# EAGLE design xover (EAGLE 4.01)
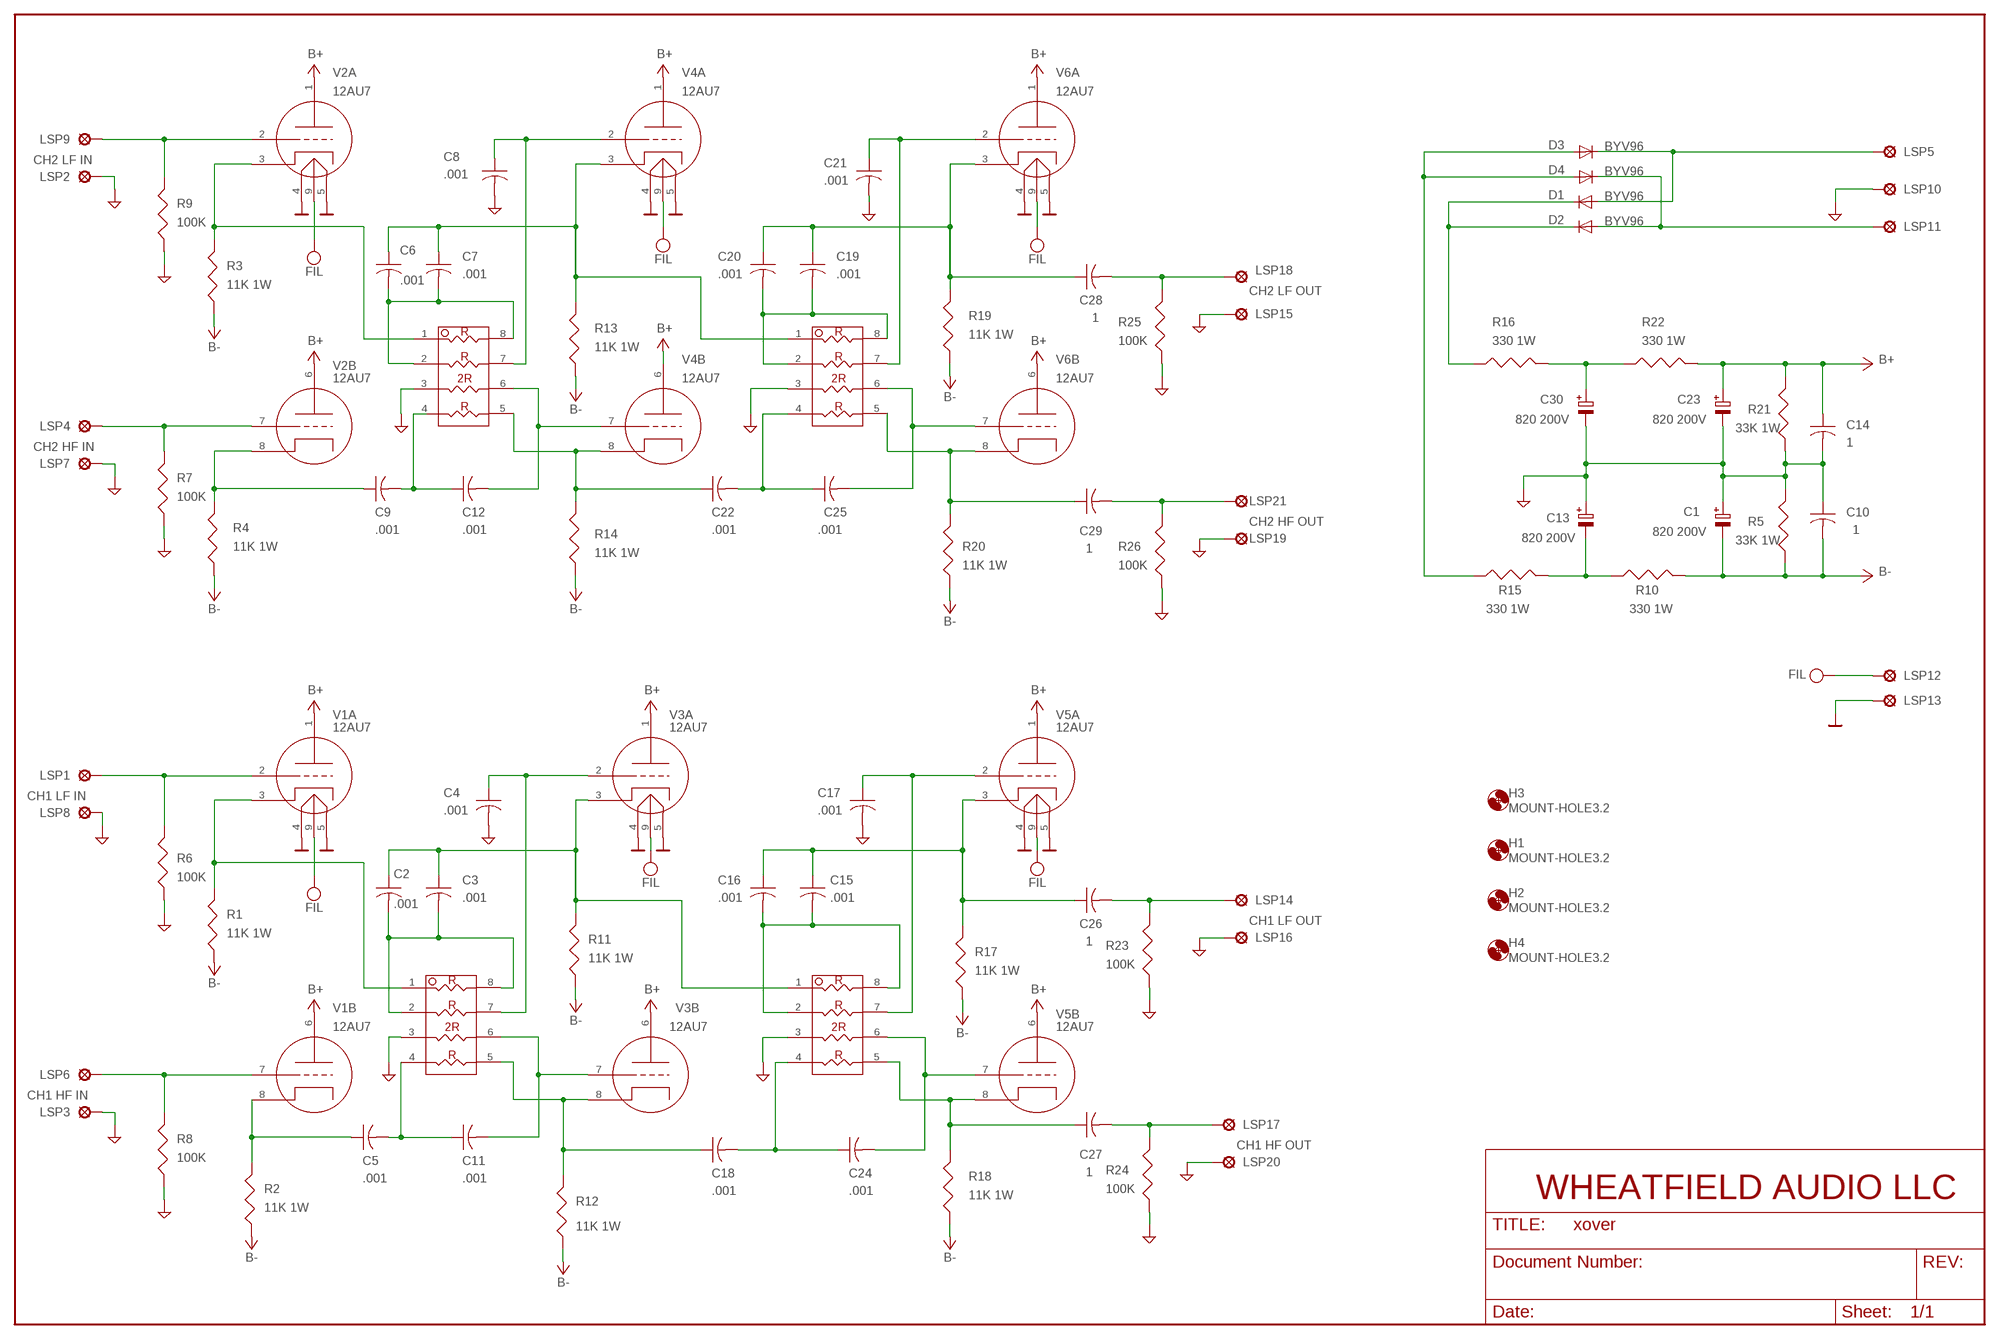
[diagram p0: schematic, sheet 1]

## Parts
C1  820 200V  C35SNAP  [C35SNAP]
C2  .001  C-US075-052X106  [C075-052X106]
C3  .001  C-US075-052X106  [C075-052X106]
C4  .001  C-US075-052X106  [C075-052X106]
C5  .001  C-US075-052X106  [C075-052X106]
C6  .001  C-US075-052X106  [C075-052X106]
C7  .001  C-US075-052X106  [C075-052X106]
C8  .001  C-US075-052X106  [C075-052X106]
C9  .001  C-US075-052X106  [C075-052X106]
C10  1  C-US275-154X316  [C275-154X316]
C11  .001  C-US075-052X106  [C075-052X106]
C12  .001  C-US075-052X106  [C075-052X106]
C13  820 200V  C35SNAP  [C35SNAP]
C14  1  C-US275-154X316  [C275-154X316]
C15  .001  C-US075-052X106  [C075-052X106]
C16  .001  C-US075-052X106  [C075-052X106]
C17  .001  C-US075-052X106  [C075-052X106]
C18  .001  C-US075-052X106  [C075-052X106]
C19  .001  C-US075-052X106  [C075-052X106]
C20  .001  C-US075-052X106  [C075-052X106]
C21  .001  C-US075-052X106  [C075-052X106]
C22  .001  C-US075-052X106  [C075-052X106]
C23  820 200V  C35SNAP  [C35SNAP]
C24  .001  C-US075-052X106  [C075-052X106]
C25  .001  C-US075-052X106  [C075-052X106]
C26  1  C-US275-154X316  [C275-154X316]
C27  1  C-US275-154X316  [C275-154X316]
C28  1  C-US275-154X316  [C275-154X316]
C29  1  C-US275-154X316  [C275-154X316]
C30  820 200V  C35SNAP  [C35SNAP]
D1  BYV96  [SOD57-10]
D2  BYV96  [SOD57-10]
D3  BYV96  [SOD57-10]
D4  BYV96  [SOD57-10]
H1  MOUNT-HOLE3.2  [3,2]
H2  MOUNT-HOLE3.2  [3,2]
H3  MOUNT-HOLE3.2  [3,2]
H4  MOUNT-HOLE3.2  [3,2]
LSP1  SE14  [SE14]
LSP2  SE14  [SE14]
LSP3  SE14  [SE14]
LSP4  SE14  [SE14]
LSP5  SE14  [SE14]
LSP6  SE14  [SE14]
LSP7  SE14  [SE14]
LSP8  SE14  [SE14]
LSP9  SE14  [SE14]
LSP10  SE14  [SE14]
LSP11  SE14  [SE14]
LSP12  SE14  [SE14]
LSP13  SE14  [SE14]
LSP14  SE14  [SE14]
LSP15  SE14  [SE14]
LSP16  SE14  [SE14]
LSP17  SE14  [SE14]
LSP18  SE14  [SE14]
LSP19  SE14  [SE14]
LSP20  SE14  [SE14]
LSP21  SE14  [SE14]
R1  11K 1W  R5W_MILLS  [R5W_MILLS]
R2  11K 1W  R5W_MILLS  [R5W_MILLS]
R3  11K 1W  R5W_MILLS  [R5W_MILLS]
R4  11K 1W  R5W_MILLS  [R5W_MILLS]
R5  33K 1W  R5W_MILLS  [R5W_MILLS]
R6  100K  R1/4W  [R1/4W]
R7  100K  R1/4W  [R1/4W]
R8  100K  R1/4W  [R1/4W]
R9  100K  R1/4W  [R1/4W]
R10  330 1W  R5W_MILLS  [R5W_MILLS]
R11  11K 1W  R5W_MILLS  [R5W_MILLS]
R12  11K 1W  R5W_MILLS  [R5W_MILLS]
R13  11K 1W  R5W_MILLS  [R5W_MILLS]
R14  11K 1W  R5W_MILLS  [R5W_MILLS]
R15  330 1W  R5W_MILLS  [R5W_MILLS]
R16  330 1W  R5W_MILLS  [R5W_MILLS]
R17  11K 1W  R5W_MILLS  [R5W_MILLS]
R18  11K 1W  R5W_MILLS  [R5W_MILLS]
R19  11K 1W  R5W_MILLS  [R5W_MILLS]
R20  11K 1W  R5W_MILLS  [R5W_MILLS]
R21  33K 1W  R5W_MILLS  [R5W_MILLS]
R22  330 1W  R5W_MILLS  [R5W_MILLS]
R23  100K  R1/4W  [R1/4W]
R24  100K  R1/4W  [R1/4W]
R25  100K  R1/4W  [R1/4W]
R26  100K  R1/4W  [R1/4W]
RM1  R_MODULE  [R_MODULE]
RM2  R_MODULE  [R_MODULE]
RM3  R_MODULE  [R_MODULE]
RM4  R_MODULE  [R_MODULE]
V1  12AU7  TRIODE_9A  [NOVAL_PCB]
V2  12AU7  TRIODE_9A  [NOVAL_PCB]
V3  12AU7  TRIODE_9A  [NOVAL_PCB]
V4  12AU7  TRIODE_9A  [NOVAL_PCB]
V5  12AU7  TRIODE_9A  [NOVAL_PCB]
V6  12AU7  TRIODE_9A  [NOVAL_PCB]

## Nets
0V: LSP13.MP V1.4 V1.5 V2.4 V2.5 V3.4 V3.5 V4.4 V4.5 V5.4 V5.5 V6.4 V6.5
GND: C1.1(+) C4.2 C8.2 C10.1 C13.1(+) C14.2 C17.2 C21.2 C23.2(-) C30.2(-) LSP2.MP LSP3.MP LSP7.MP LSP8.MP LSP10.MP LSP15.MP LSP16.MP LSP19.MP LSP20.MP R5.2 R6.1 R7.1 R8.1 R9.1 R21.1 R23.1 R24.1 R25.1 R26.1 RM1.3 RM2.3 RM3.3 RM4.3
N$1: LSP9.MP R9.2 V2.2
N$2: C9.2 C12.1 RM2.4
N$3: C19.1 C20.1 C28.1 R19.2 V6.3
N$4: LSP6.MP R8.2 V1.7
N$5: C22.1 R14.2 RM2.5 V4.8
N$6: C12.2 RM2.6 V4.7
N$7: LSP1.MP R6.2 V1.2
N$8: C19.2 C20.2 RM4.2 RM4.8
N$9: LSP4.MP R7.2 V2.7
N$10: C22.2 C25.1 RM4.4
N$11: C25.2 RM4.6 V6.7
N$12: C8.1 RM2.7 V4.2
N$13: C6.1 C7.1 R13.2 RM4.1 V4.3
N$14: C2.1 C3.1 R11.2 RM3.1 V3.3
N$15: C18.1 R12.2 RM1.5 V3.8
N$16: C9.1 R4.2 V2.8
N$17: C4.1 RM1.7 V3.2
N$19: C5.1 R2.2 V1.8
N$20: C15.1 C16.1 C26.1 R17.2 V5.3
N$21: C11.2 RM1.6 V3.7
N$22: C5.2 C11.1 RM1.4
N$23: C17.1 RM3.7 V5.2
N$24: R3.2 RM2.1 V2.3
N$25: R1.2 RM1.1 V1.3
N$26: C18.2 C24.1 RM3.4
N$27: C24.2 RM3.6 V5.7
N$28: C27.1 R18.2 RM3.5 V5.8
N$30: C28.2 LSP18.MP R25.2
N$31: C29.2 LSP21.MP R26.2
N$32: C26.2 LSP14.MP R23.2
N$33: C27.2 LSP17.MP R24.2
N$34: C6.2 C7.2 RM2.2 RM2.8
N$35: C21.1 RM4.7 V6.2
N$36: C29.1 R20.2 RM4.5 V6.8
N$39: C2.2 C3.2 RM1.2 RM1.8
N$40: D1.A D3.K(C) LSP5.MP
N$42: D1.K(C) D2.K(C) R16.1
N$43: D2.A D4.K(C) LSP11.MP
N$44: C30.1(+) R16.2 R22.1
N$46: D3.A D4.A R15.1
N$47: C13.2(-) R10.1 R15.2
N$50: C15.2 C16.2 RM3.2 RM3.8
V+: C14.1 C23.1(+) R21.2 R22.2 V1.1 V1.6 V2.1 V2.6 V3.1 V3.6 V4.1 V4.6 V5.1 V5.6 V6.1 V6.6 ; supply symbol labelled B+
V-: C1.2(-) C10.2 R1.1 R2.1 R3.1 R4.1 R5.1 R10.2 R11.1 R12.1 R13.1 R14.1 R17.1 R18.1 R19.1 R20.1 ; supply symbol labelled B-
VCC: LSP12.MP V1.9 V2.9 V3.9 V4.9 V5.9 V6.9 ; supply symbol labelled FIL

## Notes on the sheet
- CH2 LF IN
- CH2 LF OUT
- CH2 HF IN
- CH2 HF OUT
- CH1 LF IN
- CH1 LF OUT
- CH1 HF IN
- CH1 HF OUT
- WHEATFIELD AUDIO LLC

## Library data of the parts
C1 C13 C23 C30 = wheat:C35SNAP: CAP, 35MM SNAP MOUNT
C2-C12 C14-C22 C24-C29 = rcl:C-US: CAPACITOR, American symbol
D1-D4 = diode:BYV96: DIODE
H1-H4 = holes:MOUNT-HOLE: MOUNTING HOLE with drill center marker
LSP1-LSP21 = solpad:SE14: SOLDER PAD
R1-R5 R10-R22 = wheat:R5W_MILLS: RESISTOR, 5W WIREWOUND, MILLS
R6-R9 R23-R26 = wheat:R1/4W: RESISTOR, 1/4W THM
RM1-RM4 = wheat:R_MODULE: RESISTOR MODULE DIP8
V1-V6 = wheat:TRIODE_9A: TRIODE, BASE 9A 12AU7, 12AX7, ETC.

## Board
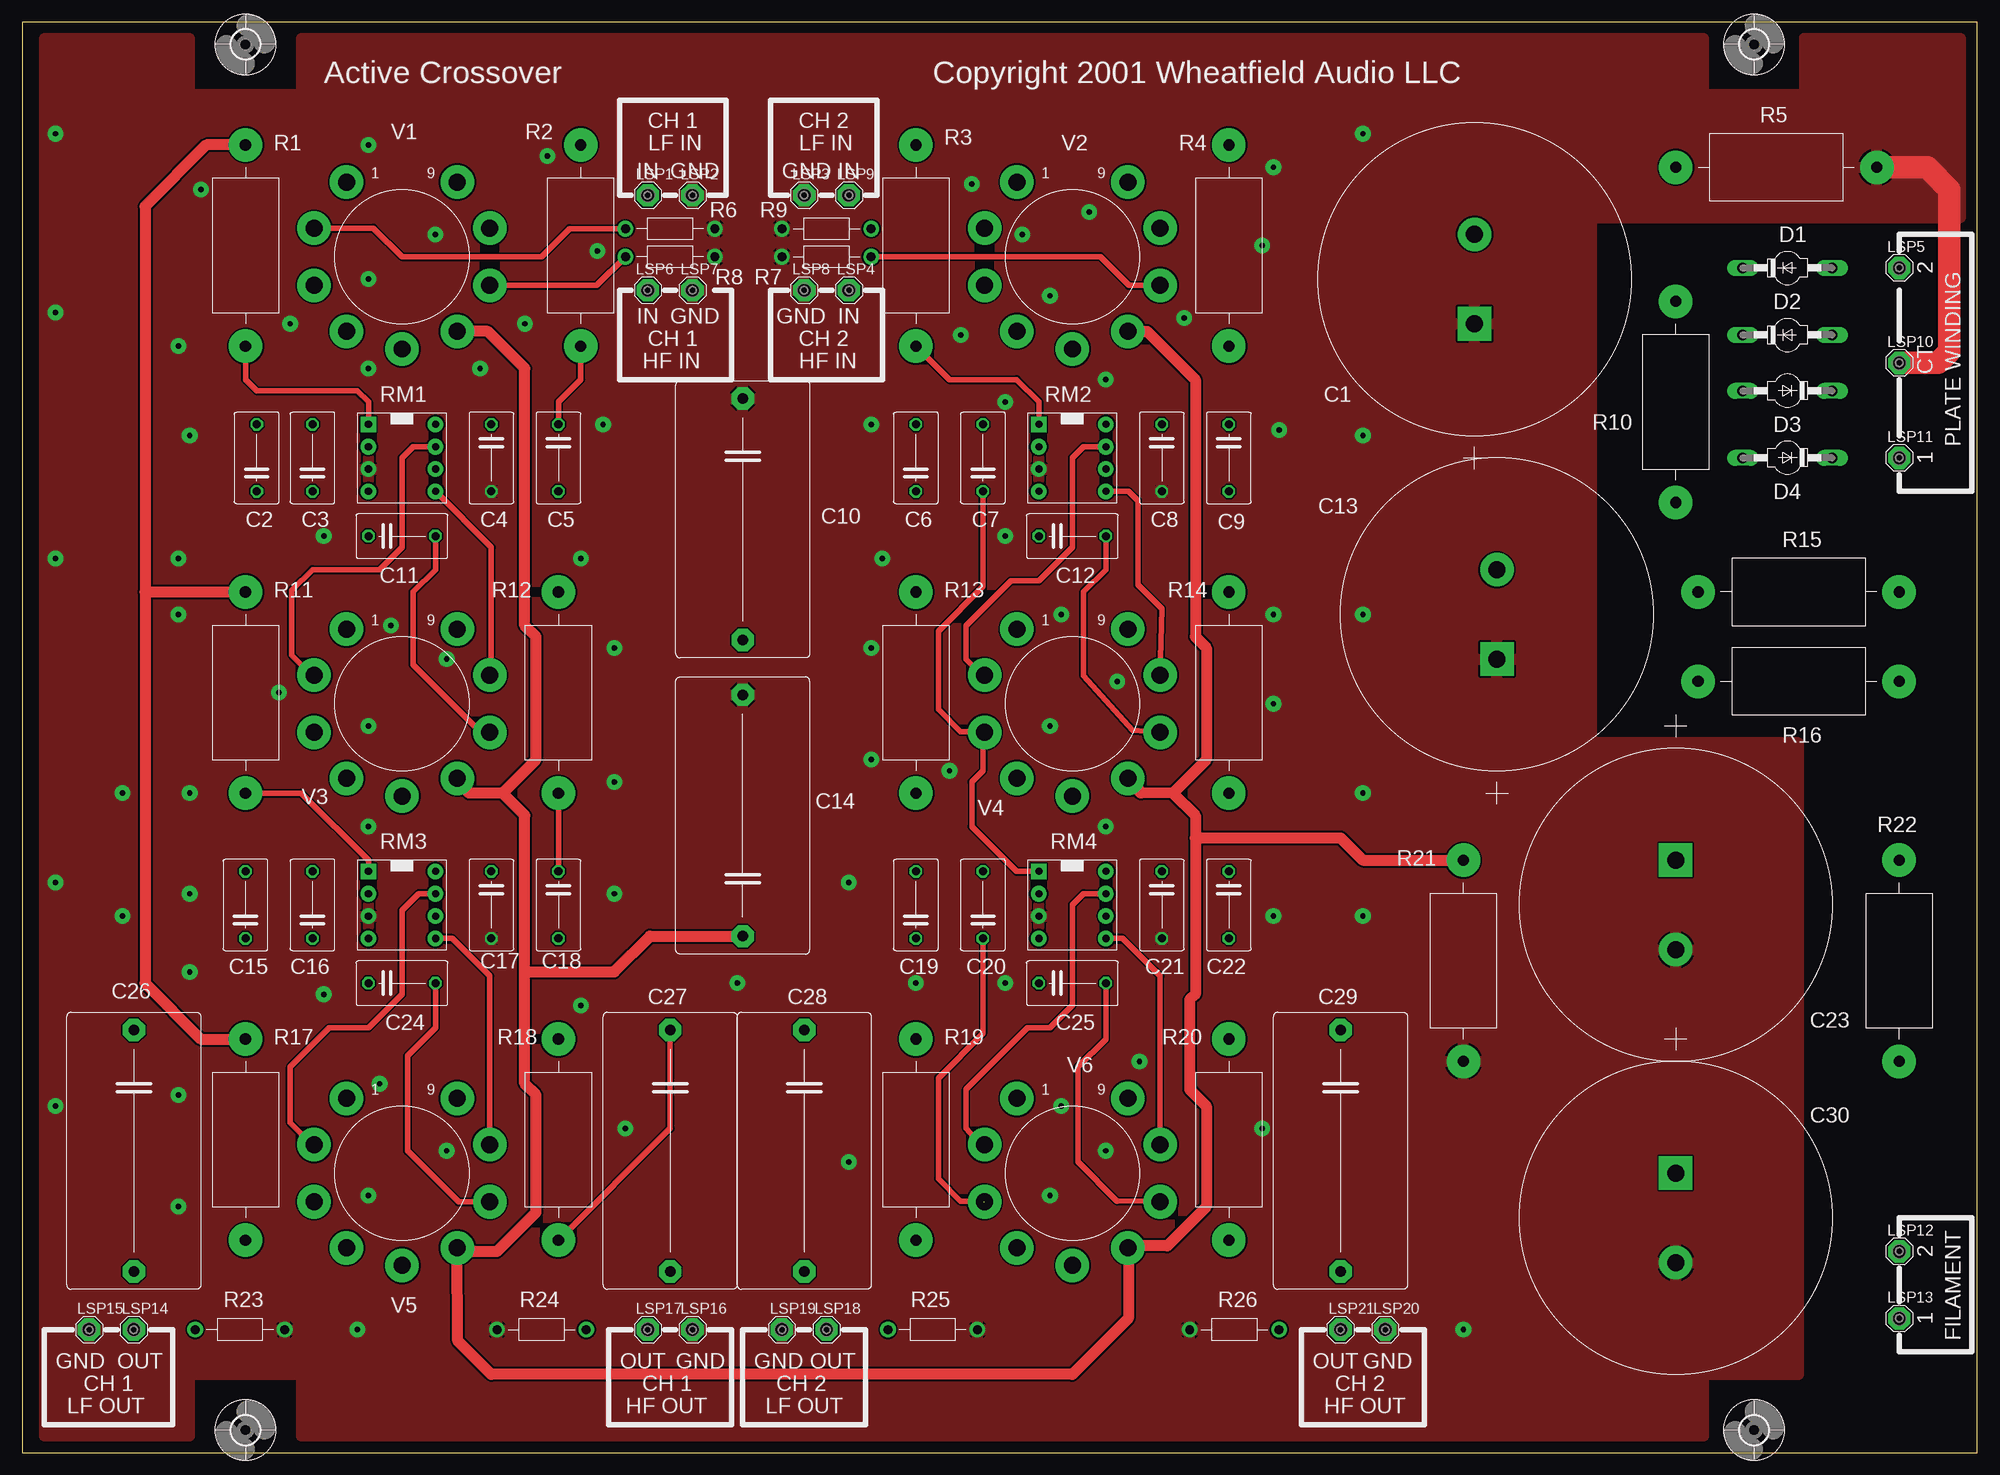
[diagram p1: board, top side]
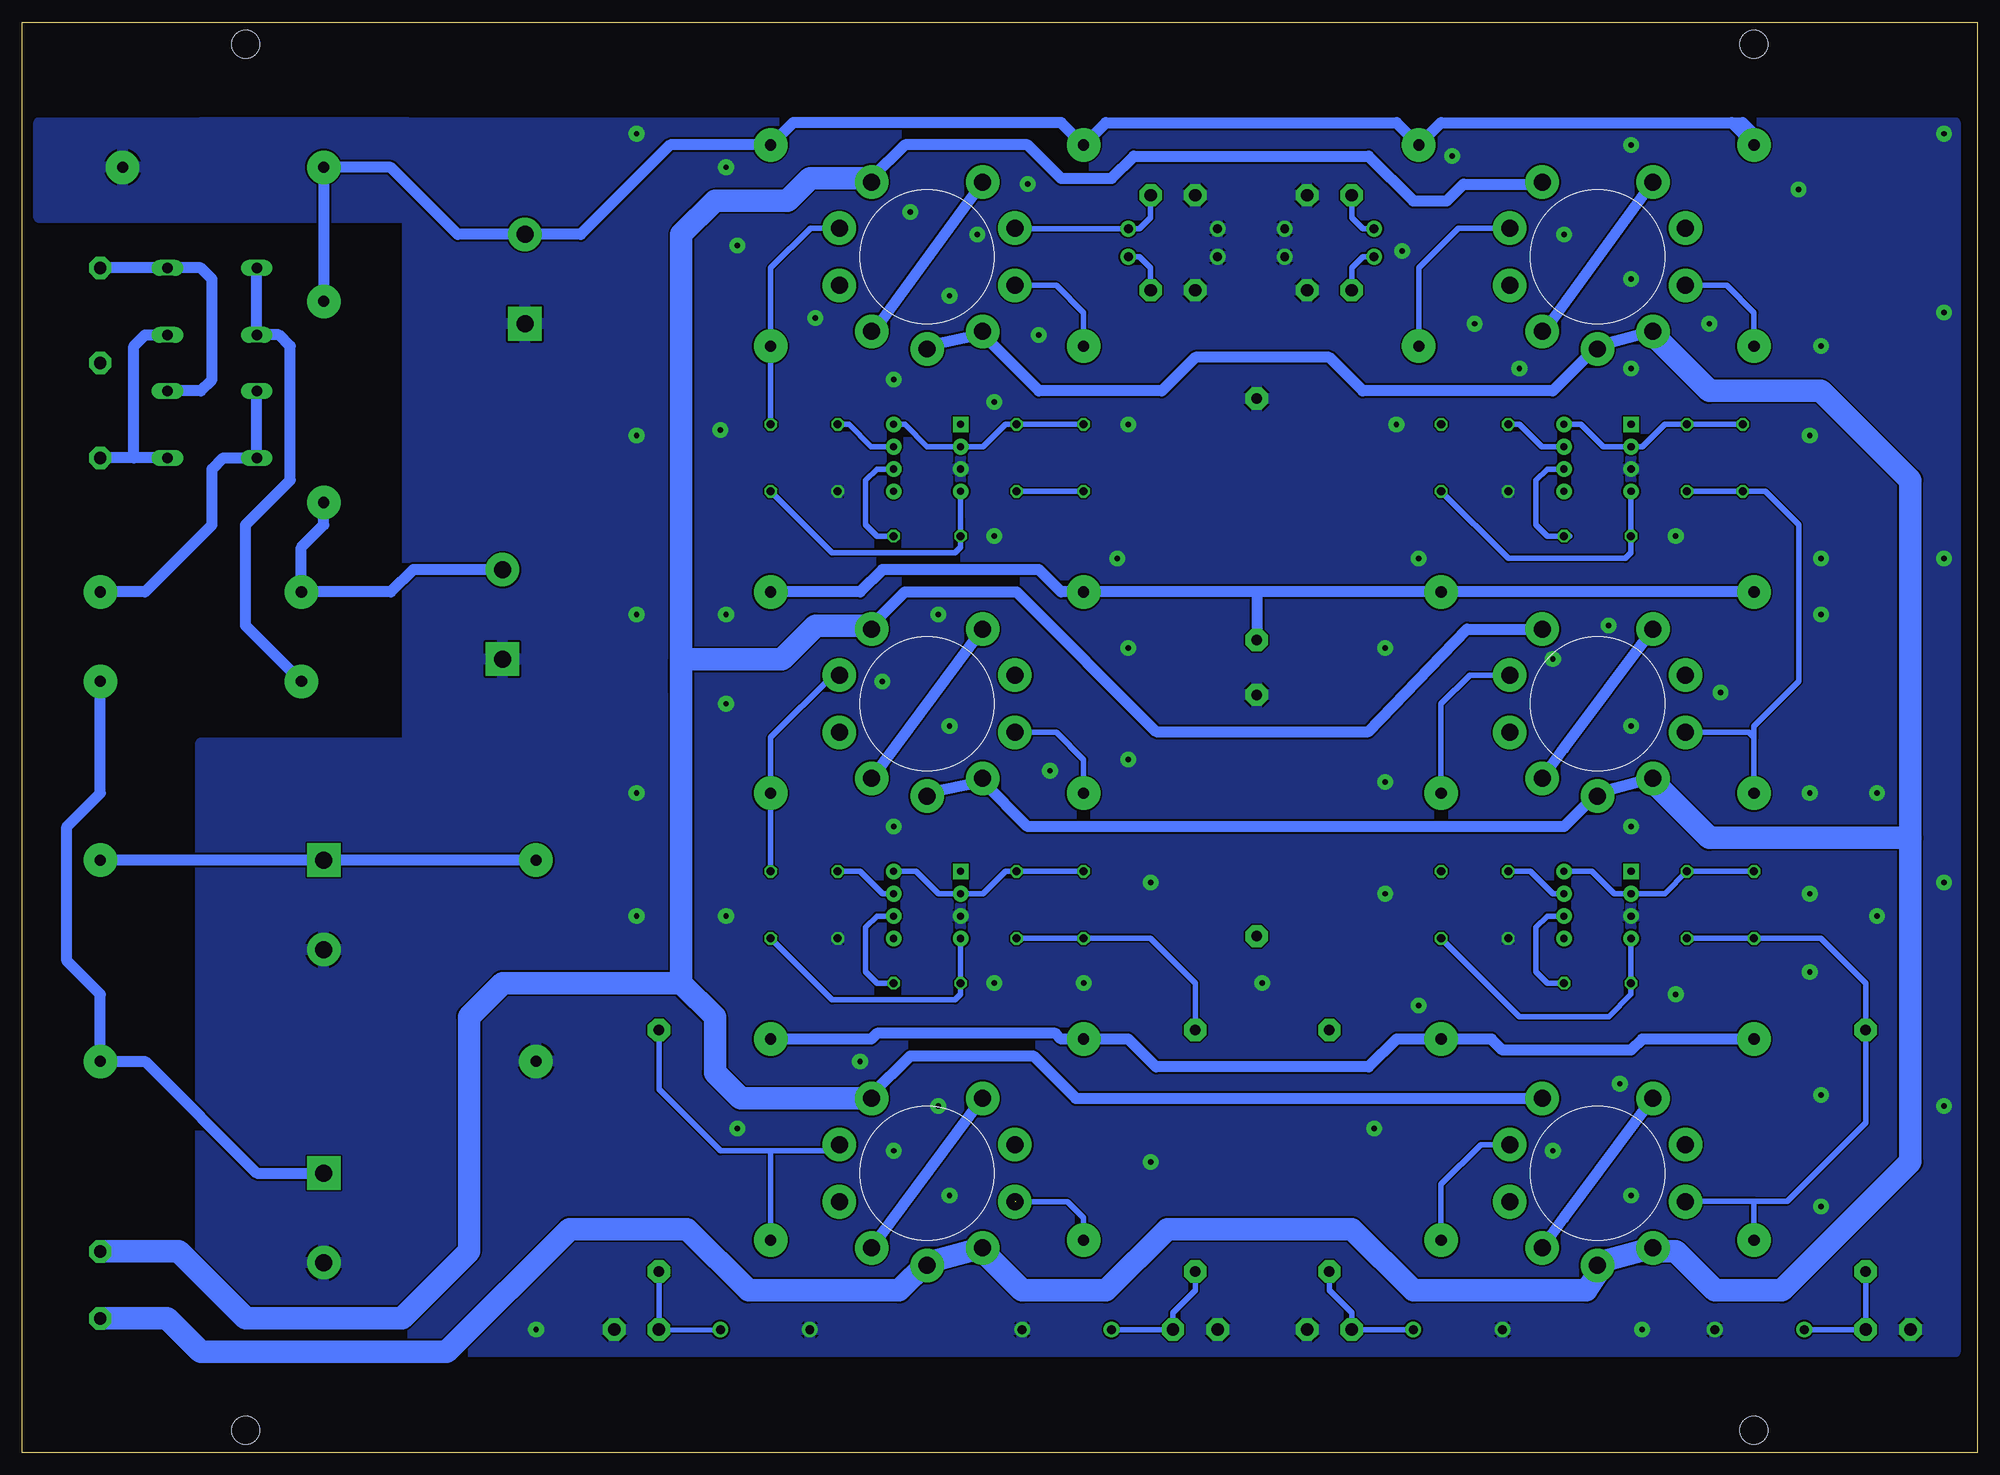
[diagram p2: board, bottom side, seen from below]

Size 222.27 x 162.56 mm. Coordinates in mm from the lower left corner, seen from the top.
Outline: 222.26,0 0,0 0.01,162.55 222.27,162.56 222.26,0
Outline: 220.99,0 222.26,0
Copper layers used: Top, Bottom
bKeepout: area 0,0 to 221,7.6; area 0,152.4 to 221,160

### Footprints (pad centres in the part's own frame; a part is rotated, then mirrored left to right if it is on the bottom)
C35SNAP = drill 1.93 pad 3.81 square: 1 -5.08,0 | drill 1.93 pad 3.81 round: 2 5.08,0
C075-052X106 = drill 0.914 octagon: 1 -3.81,0; 2 3.81,0
C275-154X316 = drill 1.194 pad 2.54 octagon: 1 -13.716,0; 2 13.716,0
SOD57-10 = drill 1.194 long: A 5.08,0; K -5.08,0
3,2 = hole 3.2: 0,0
SE14 = drill 1.397 pad 2.54 octagon: MP 0,0
R5W_MILLS = drill 1.27 pad 3.81 round: 1 0,0; 2 22.86,0
R1/4W = drill 1.016 pad 1.778 round: 1 0,0; 2 10.16,0
R_MODULE = drill 0.813 pad 1.778 square: 1 0,0 | drill 0.813 pad 1.778 round: 2 0,-2.54; 3 0,-5.08; 4 0,-7.62; 5 7.62,-7.62; 6 7.62,-5.08; 7 7.62,-2.54; 8 7.62,0
NOVAL_PCB = drill 1.93 pad 3.81 round: 1 6.299,-8.484; 2 9.982,-3.251; 3 9.982,3.251; 4 6.299,8.484; 5 0,10.49; 6 -6.299,8.484; 7 -9.982,3.251; 8 -9.982,-3.251; 9 -6.299,-8.484

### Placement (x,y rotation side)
C1  165.11,133.35 90 top
C2  26.68,113.03 90 top
C3  33.03,113.03 90 top
C4  53.35,113.03 270 top
C5  60.97,113.03 270 top
C6  101.61,113.03 90 top
C7  109.23,113.03 90 top
C8  129.55,113.03 270 top
C9  137.17,113.03 270 top
C10  81.92,106.05 270 top
C11  43.19,104.14 0 top
C12  119.39,104.14 0 top
C13  167.65,95.25 90 top
C14  81.92,72.39 90 top
C15  25.41,62.23 90 top
C16  33.03,62.23 90 top
C17  53.35,62.23 270 top
C18  60.97,62.23 270 top
C19  101.61,62.23 90 top
C20  109.23,62.23 90 top
C21  129.55,62.23 270 top
C22  137.17,62.23 270 top
C23  187.97,62.23 270 top
C24  43.19,53.34 0 top
C25  119.39,53.34 0 top
C26  12.71,34.29 270 top
C27  73.67,34.29 270 top
C28  88.91,34.29 270 top
C29  149.87,34.29 270 top
C30  187.97,26.67 270 top
D1  200.67,134.62 0 top
D2  200.67,127 0 top
D3  200.67,120.65 180 top
D4  200.67,113.03 180 top
H1  25.41,160.02 0 top
H2  196.86,160.02 0 top
H3  25.41,2.54 0 top
H4  196.86,2.54 0 top
LSP1  71.13,142.88 0 top
LSP2  76.21,142.88 0 top
LSP3  88.91,142.88 0 top
LSP4  93.99,132.08 0 top
LSP5  213.37,134.62 0 top
LSP6  71.13,132.08 0 top
LSP7  76.21,132.08 0 top
LSP8  88.91,132.08 0 top
LSP9  93.99,142.88 0 top
LSP10  213.37,123.83 0 top
LSP11  213.37,113.03 0 top
LSP12  213.37,22.86 0 top
LSP13  213.37,15.24 0 top
LSP14  12.71,13.97 0 top
LSP15  7.63,13.97 0 top
LSP16  76.21,13.97 0 top
LSP17  71.13,13.97 0 top
LSP18  91.45,13.97 0 top
LSP19  86.37,13.97 0 top
LSP20  154.95,13.97 0 top
LSP21  149.87,13.97 0 top
R1  25.41,148.59 270 top
R2  63.51,148.59 270 top
R3  101.61,148.59 270 top
R4  137.17,148.59 270 top
R5  187.97,146.05 0 top
R6  78.75,139.06 180 top
R7  86.37,135.89 0 top
R8  78.75,135.89 180 top
R9  86.37,139.06 0 top
R10  187.97,107.95 90 top
R11  25.41,97.79 270 top
R12  60.97,97.79 270 top
R13  101.61,97.79 270 top
R14  137.17,97.79 270 top
R15  213.37,97.79 180 top
R16  190.51,87.63 0 top
R17  25.41,46.99 270 top
R18  60.97,46.99 270 top
R19  101.61,46.99 270 top
R20  137.17,46.99 270 top
R21  163.84,44.45 90 top
R22  213.37,44.45 90 top
R23  29.85,13.97 180 top
R24  53.98,13.97 0 top
R25  108.59,13.97 180 top
R26  132.72,13.97 0 top
RM1  39.38,116.84 0 top
RM2  115.58,116.84 0 top
RM3  39.38,66.04 0 top
RM4  115.58,66.04 0 top
V1  43.19,135.89 180 top
V2  119.39,135.89 180 top
V3  43.19,85.09 180 top
V4  119.39,85.09 180 top
V5  43.19,31.75 180 top
V6  119.39,31.75 180 top

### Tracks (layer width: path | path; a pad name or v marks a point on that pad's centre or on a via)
0V
  Bottom 0.61: V4.4 113.09,76.78 113.04,76.83 113.04,76.2
  Bottom 1.27: 113.09,127.05 V2.4 | 43.19,74.93 V3.5 | 43.19,74.93 V3.4 36.61,75.97 | 119.39,21.59 V6.5 | 43.19,20.32 V5.5 43.19,21.59 36.84,22.86 | 43.19,74.93 47,71.12 107.96,71.12 113.04,76.2 119.39,74.93 V4.5 | 113.09,127.05 106.69,120.65 92.72,120.65 88.91,124.46 73.67,124.46 69.86,120.65 48.27,120.65 43.52,125.4 V1.5 43.19,125.73 V1.4 36.88,127.43 36.86,127.05 36.83,127.02 36.84,127 | V2.5 119.39,125.73 113.09,127.05 | 113.04,22.86 V6.4
  Bottom 2.54: V6.4 119.39,21.59 122.56,18.41 139.71,18.41 146.69,25.4 160.03,25.4 174,11.43 201.94,11.43 205.75,15.24 LSP13.MP | V5.4 43.19,21.59 43.19,20.32 44.46,18.41 64.14,18.41 71.13,25.4 92.08,25.4 99.07,18.41 108.59,18.41 113.04,22.86 | 36.84,22.86 34.3,22.86 29.85,18.41 22.23,18.41 7.63,33.02 7.63,69.85 | 36.84,76.2 36.61,75.97 30.49,69.85 7.63,69.85 | 7.63,69.85 7.63,110.49 17.79,120.65 30.49,120.65 36.84,127
GND  (via drill 0.61 pad 1.78)
  Top 2.54: LSP10.MP 217.81,123.83 219.08,125.09 219.08,143.51 216.54,146.05 R5.2
  other vias: 3.82,149.86 3.82,129.54 20.33,143.51 39.38,148.59 30.49,128.27 17.79,125.73 39.38,133.35 47,138.43 59.7,147.32 142.88,116.2 57.16,128.27 65.41,136.53 52.08,123.19 39.38,123.19 19.06,115.57 3.82,101.6 17.79,101.6 34.3,104.14 63.51,101.6 66.05,116.84 17.79,95.25 29.22,86.36 41.92,93.98 48.27,90.17 39.38,82.55 67.32,91.44 67.32,76.2 67.32,63.5 81.29,53.34 63.51,50.8 34.3,52.07 19.06,74.93 11.44,74.93 3.82,64.77 11.44,60.96 19.06,63.5 19.06,54.61 39.38,71.12 3.82,39.37 17.79,40.64 17.79,27.94 38.11,13.97 39.38,29.21 40.65,41.91 48.27,34.29 68.59,36.83 93.99,33.02 101.61,53.34 111.77,53.34 116.85,29.21 118.12,39.37 123.2,34.29 127.01,44.45 140.98,36.83 163.84,13.97 152.41,60.96 142.25,60.96 152.41,74.93 142.25,85.09 142.25,95.25 152.41,95.25 123.2,71.12 124.47,87.63 118.12,95.25 116.85,82.55 105.42,77.47 96.53,78.74 93.99,64.77 96.53,91.44 97.8,101.6 107.96,144.15 116.85,131.44 106.69,127 96.53,116.84 111.77,119.38 123.2,121.92 113.67,138.43 121.29,140.97 132.09,128.91 152.41,115.57 140.98,137.16 142.25,146.05 152.41,149.86 111.77,104.14
  pour Bottom: 2.55,11.43 201.94,11.43 201.94,80.64 178.44,80.64 178.44,140.34 220.35,140.34 220.35,151.13 178.44,151.13 201.94,151.13 2.55,151.13
  pour Top: 2.55,160.66 2.55,1.91 19.06,1.91 19.06,8.89 31.76,8.89 31.76,1.91 191.14,1.91 191.14,8.89 201.94,8.89 201.94,80.64 178.44,80.64 178.44,140.34 220.35,140.34 220.35,160.66 202.57,160.66 202.57,154.31 191.14,154.31 191.14,160.66 31.76,160.66 31.76,154.31 19.06,154.31 19.06,160.66
N$1
  Bottom 0.61: V2.2 109.94,139.14 109.23,139.06 R9.2 95.26,139.06 93.99,140.34 LSP9.MP
N$2
  Bottom 0.61: 115.58,106.05 C12.1 | 115.58,106.05 115.58,102.87 116.21,102.23 130.18,102.23 C9.2 | 115.58,106.05 RM2.4
N$3  (1 unrouted)
  Top 0.61: C20.1 109.23,47.62 104.15,42.55 104.15,31.11 106.69,28.57 109.23,28.57 109.3,28.5
  Bottom 0.61: V6.3 103.44,28.5 101.61,26.67 R19.2 | C20.1 C19.1 93.99,58.42 88.91,53.34 C28.1
N$4
  Top 0.61: V1.7 65.34,132.64 R8.2
  Bottom 0.61: R8.2 69.86,135.89 71.13,134.62 LSP6.MP
N$5
  Top 0.61: V4.8 129.55,95.89 126.83,98.6 126.83,108.13 125.74,109.22 RM2.5
  Bottom 0.61: C22.1 R14.2 137.17,81.28 130.11,88.34 V4.8
N$6
  Top 0.61: V4.7 126.19,82.09 120.66,88.27 120.66,97.79 123.2,100.33 C12.2
  Bottom 0.61: C12.2 125.1,104.14 126.37,105.41 126.37,110.49 125.1,111.76 RM2.6
N$7
  Top 0.61: V1.2 39.94,139.14 43.19,135.89 59.06,135.89 62.24,139.06 R6.2
  Bottom 0.61: R6.2 69.86,139.06 71.13,140.34 LSP1.MP
N$8
  Bottom 0.61: C19.2 C20.2 110.5,66.04 113.04,63.5 RM4.2 118.12,63.5 120.66,66.04 RM4.8
N$9
  Top 0.61: V2.7 125.81,132.64 122.56,135.89 R7.2
  Bottom 0.61: LSP4.MP 93.99,134.62 95.26,135.89 R7.2
N$10
  Bottom 0.61: C22.2 130.18,51.44 116.21,51.44 115.58,52.07 C25.1 RM4.4
N$11
  Top 0.61: C25.2 123.2,46.99 120.02,43.81 120.02,33.02 124.47,28.57 129.4,28.6 | 129.4,28.6 129.41,28.58 | V6.7 129.4,28.59 129.4,28.6
  Top 1.27: 129.36,28.45 129.38,28.44 V6.7
  Bottom 0.61: C25.2 125.1,53.34 126.37,54.61 126.37,59.69 125.1,60.96 RM4.6
N$12
  Top 0.61: V4.2 109.15,88.34 107.32,90.17 107.32,93.98 112.4,99.06 115.58,99.06 119.39,102.87 119.39,113.03 120.66,114.3 RM2.7
  Bottom 0.61: C8.1 128.28,116.84 125.74,114.3 RM2.7
N$13
  Top 0.61: C7.1 109.23,98.42 104.15,93.34 104.15,84.45 106.69,81.92 109.23,81.92 | V4.3 109.4,82.09 109.23,81.92 | 109.23,81.92 109.23,77.47 107.96,76.2 107.96,71.12 113.04,66.04 RM4.1
  Bottom 0.61: V4.3 104.71,81.84 101.61,78.74 R13.2 | C7.1 C6.1
N$14
  Top 0.61: R11.2 31.76,74.93 39.38,67.31 RM3.1
  Bottom 0.61: C2.1 C3.1 24.14,109.22 20.33,105.41 20.33,87.63 25.41,82.55 25.41,81.28 | R11.2 25.41,81.28 | V3.3 25.97,81.84 25.41,81.28
N$15
  Top 0.61: RM1.5 53.35,102.87 53.35,87.63 53.17,87.81 V3.8 | C18.1 R12.2
  Bottom 0.61: V3.8 57.72,88.34 60.97,85.09 R12.2
N$16
  Bottom 0.61: V2.8 132.65,139.14 137.17,134.62 R4.2 C9.1
N$17
  Top 0.61: V3.2 33.03,88.27 30.66,90.63 30.66,97.97 33.03,100.33 40.65,100.33 43.19,102.87 43.19,113.03 44.46,114.3 RM1.7
  Bottom 0.61: C4.1 52.08,116.84 49.54,114.3 RM1.7
N$19
  Top 0.61: C5.1 60.97,119.38 63.51,121.92 R2.2
  Bottom 0.61: V1.8 58.99,139.14 63.51,134.62 R2.2
N$20
  Bottom 0.61: C16.1 C15.1 17.79,58.42 12.71,53.34 12.71,48.26 | 12.71,48.26 C26.1 | V5.3 32.95,28.5 33.03,28.57 25.41,28.57 | 25.41,28.57 21.6,28.57 12.71,37.47 12.71,48.26 | R17.2 25.41,28.57
N$21
  Top 0.61: C11.2 47,100.33 44.46,97.79 44.46,89.53 51.44,82.55 53.35,82.55 53.17,82.37 V3.7
  Bottom 0.61: 46.36,104.14 C11.2 48.9,104.14 50.17,105.41 50.17,110.49 48.9,111.76 RM1.6
N$22
  Bottom 0.61: RM1.4 C11.1 39.38,102.23 40.01,101.6 53.35,101.6 C5.2
N$23
  Top 0.61: V5.2 32.95,35 30.49,37.47 30.49,43.81 34.93,48.26 39.38,48.26 43.19,52.07 43.19,61.59 45.09,63.5 RM3.7
  Bottom 0.61: C17.1 50.81,66.04 48.27,63.5 RM3.7
N$24
  Top 0.61: R3.2 105.42,121.92 113.04,121.92 115.58,119.38 RM2.1
  Bottom 0.61: V2.3 104.71,132.64 101.61,129.54 R3.2
N$25
  Top 0.61: R1.2 25.41,121.92 26.68,120.65 38.11,120.65 39.38,119.38 RM1.1
  Bottom 0.61: V1.3 28.51,132.64 25.41,129.54 R1.2
N$26
  Bottom 0.61: C18.2 52.08,49.53 41.92,49.53 39.38,52.07 C24.1 RM3.4
N$27
  Top 0.61: V5.7 49.61,28.5 43.82,34.29 43.82,45.09 47,48.26 C24.2
  Bottom 0.61: C24.2 48.9,53.34 50.17,54.61 50.17,59.69 48.9,60.96 RM3.6
N$28
  Top 0.61: V5.8 53.17,54.15 48.9,58.42 RM3.5 | C27.1 73.67,36.83 R18.2
  Bottom 0.61: V5.8 56.45,35 60.97,30.48 R18.2
N$30
  Bottom 0.61: C28.2 88.91,18.41 91.45,15.88 LSP18.MP R25.2
N$31
  Bottom 0.61: 149.87,13.9 LSP21.MP | 149.87,13.9 C29.2 | 149.87,13.9 150.01,13.76 | R26.2 149.87,13.9
N$32
  Bottom 0.61: C26.2 LSP14.MP R23.2
N$33
  Bottom 0.61: C27.2 73.67,18.41 71.13,15.88 LSP17.MP R24.2
N$34
  Bottom 0.61: C6.2 C7.2 110.5,116.84 113.04,114.3 RM2.2 119.39,114.3 121.93,116.84 RM2.8
N$35
  Top 0.61: V6.2 109.4,34.47 107.32,36.83 107.32,41.27 114.31,48.26 116.85,48.26 119.39,50.8 119.39,62.23 120.66,63.5 RM4.7
  Bottom 0.61: C21.1 127.01,66.04 124.47,63.5 RM4.7
N$36
  Top 0.61: V6.8 129.37,54.15 125.1,58.42 RM4.5
  Bottom 0.61: V6.8 129.47,35 130.18,34.29 137.17,34.29 | 137.17,22.86 R20.2 137.17,34.29 | C29.1 149.87,41.27 142.88,34.29 137.17,34.29
N$39
  Bottom 0.61: C2.2 C3.2 35.57,116.84 38.11,114.3 RM1.2 42.55,114.3 45.09,116.84 RM1.8
N$40
  Bottom 1.27: LSP5.MP D1.A 201.94,134.62 200.67,133.35 200.67,121.92 201.94,120.65 D3.K
N$42
  Bottom 1.27: D1.K D2.K 193.05,127 191.78,125.73 191.78,110.49 196.86,105.41 196.86,93.98 R16.1
N$43
  Bottom 1.27: 209.56,113.03 LSP11.MP | D4.K 209.56,113.03 | 209.56,113.03 209.56,125.73 208.29,127 D2.A
N$44
  Bottom 1.27: R16.2 213.37,74.93 217.18,71.12 217.18,55.88 213.37,52.07 R22.1 208.29,44.45 195.59,31.75 C30.1
N$46
  Bottom 1.27: D3.A D4.A 199.4,113.03 200.67,111.76 200.67,105.41 208.29,97.79 R15.1
N$47
  Bottom 1.27: R10.1 187.97,105.41 190.51,102.87 R15.2 180.35,97.79 177.81,100.33 C13.2
N$50
  Bottom 0.61: C15.2 C16.2 35.57,63.5 RM3.2 | RM3.2 40.01,63.5 | RM3.2 41.28,63.5 43.82,66.04 RM3.8
V+
  Top 1.27: V1.6 52.94,127.41 57.16,123.19 57.16,93.98 58.43,92.71 58.43,78.74 54.62,74.93 | V2.6 127.87,127.41 133.36,121.92 133.36,92.71 134.63,91.44 134.63,78.74 130.82,74.93 | 127.2,74.96 126.94,75.33 | 54.62,74.93 50.81,74.93 49.49,76.25 V3.6 | 54.62,74.93 57.16,72.39 57.16,54.61 | 130.82,74.93 127.2,74.96 | 130.82,74.93 133.36,72.39 133.36,69.85 | 133.36,69.85 133.36,52.07 132.72,51.44 132.72,41.27 134.63,39.37 134.63,27.94 130.18,23.5 127.01,23.5 V6.6 125.69,21.64 125.74,21.59 | 125.74,21.59 125.74,15.24 119.39,8.89 53.35,8.89 49.54,12.7 V5.6 49.54,22.86 53.98,22.86 58.43,27.3 58.43,40.64 57.16,41.91 57.16,54.61 | 57.16,54.61 67.32,54.61 71.38,58.67 C14.1 | R21.2 152.41,67.31 149.87,69.85 133.36,69.85 | V4.6 125.71,76.6 125.81,76.64 125.76,76.55 125.76,76.64 125.67,76.59 127.16,74.93 127.19,74.97 127.2,74.96 | 127.2,74.96 | 125.74,21.59 125.74,21.66 125.76,21.69 125.74,21.71 125.74,21.59
  Bottom 0.61: V4.6 125.7,76.62 125.72,76.58
  Bottom 1.27: V1.6 49.54,127 V1.1 | V2.6 125.74,127 V2.1 | R22.2 C23.1 R21.2 | 125.72,76.58 V4.1 | V3.1 47,80.01 V3.6 | V5.1 47,26.67 V5.6 | V6.1 125.1,24.13 V6.6
V-
  Top 1.27: R17.1 20.33,46.99 13.98,53.34 13.98,97.79 | 13.98,97.79 R11.1 | R1.1 20.96,148.59 13.98,141.6 13.98,97.79
  Bottom 1.27: R11.1 R12.1 81.92,97.79 | R14.1 127.01,97.79 124.47,100.33 106.69,100.33 104.15,97.79 R13.1 81.92,97.79 | 82.18,92.33 C10.2 | 81.92,97.79 81.92,92.08 82.18,92.33 | 82.18,92.33 82.3,92.33 | 55.25,46.99 59.7,46.99 60.97,48.26 R18.1 | R18.1 66.05,46.99 69.22,43.81 93.35,43.81 96.53,46.99 R19.1 104.15,46.99 104.78,47.62 125.1,47.62 125.74,46.99 R20.1 | R10.2 R5.1 180.35,146.05 172.73,138.43 C1.2 158.76,138.43 148.6,148.59 R4.1 134.63,151.13 104.15,151.13 R3.1 99.07,151.13 66.05,151.13 R2.1 60.97,151.13 27.95,151.13 | 27.95,151.13 R1.1 25.41,149.86 26.68,151.13 27.95,151.13 | R17.1 38.11,46.99 39.38,45.72 53.98,45.72 55.25,46.99 | 55.25,46.99 R18.1
VCC
  Bottom 0.61: 125.74,144.78 125.68,144.57
  Bottom 1.27: V1.9 49.49,144.2 49.54,144.15 58.43,144.15 60.33,142.24 64.14,142.24 69.22,147.32 95.89,147.32 98.43,144.78 104.15,144.78 107.96,148.59 121.93,148.59 125.74,144.78 | V3.9 58.02,93.57 69.22,81.92 93.35,81.92 109.23,97.79 121.93,97.79 125.74,93.98 125.69,93.93 V4.9 | V5.9 102.47,40.23 107.32,45.09 121.29,45.09 125.74,40.64 125.74,40.65 125.69,40.06 V6.9 | 125.68,144.57 125.66,144.38 125.69,144.73 125.71,144.43 V2.9
  Bottom 2.54: V6.9 140.57,40.23 143.52,43.18 143.52,49.53 147.33,53.34 | 147.33,53.34 167.65,53.34 171.46,49.53 171.46,22.86 179.08,15.24 196.86,15.24 204.48,22.86 LSP12.MP | 125.74,93.98 132.09,93.98 135.9,90.17 147.33,90.17 147.33,86.36 | 147.33,86.36 147.33,53.34 | 125.74,144.78 132.72,144.78 135.26,142.24 143.52,142.24 147.33,138.43 147.33,86.36

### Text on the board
tNames: Active Crossover | Copyright 2001 Wheatfield Audio LLC | CH 1 | CH 2 | LF IN | LF IN | IN | GND | GND | IN | 2 | IN | GND | GND | IN | CH 1 | CH 2 | HF IN | HF IN | CT | PLATE WINDING | 1 | 2 | 1 | FILAMENT | GND | OUT | OUT | GND | GND | OUT | OUT | GND | CH 1 | CH 1 | CH 2 | CH 2 | LF OUT | HF OUT | LF OUT | HF OUT
Document: 6.40 | 6.30 | 0.10 | 0.00 | 0.00 | 1.00 | 7.75 | 8.75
